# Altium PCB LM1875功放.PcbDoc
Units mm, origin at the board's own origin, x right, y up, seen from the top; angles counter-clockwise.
Board outline 134 x 60 mm, 2 copper layers (Top Layer, Bottom Layer); 94 components, 42 nets, 227 pads, 66 vias.
Unrouted connection lines stored in the file: 1.
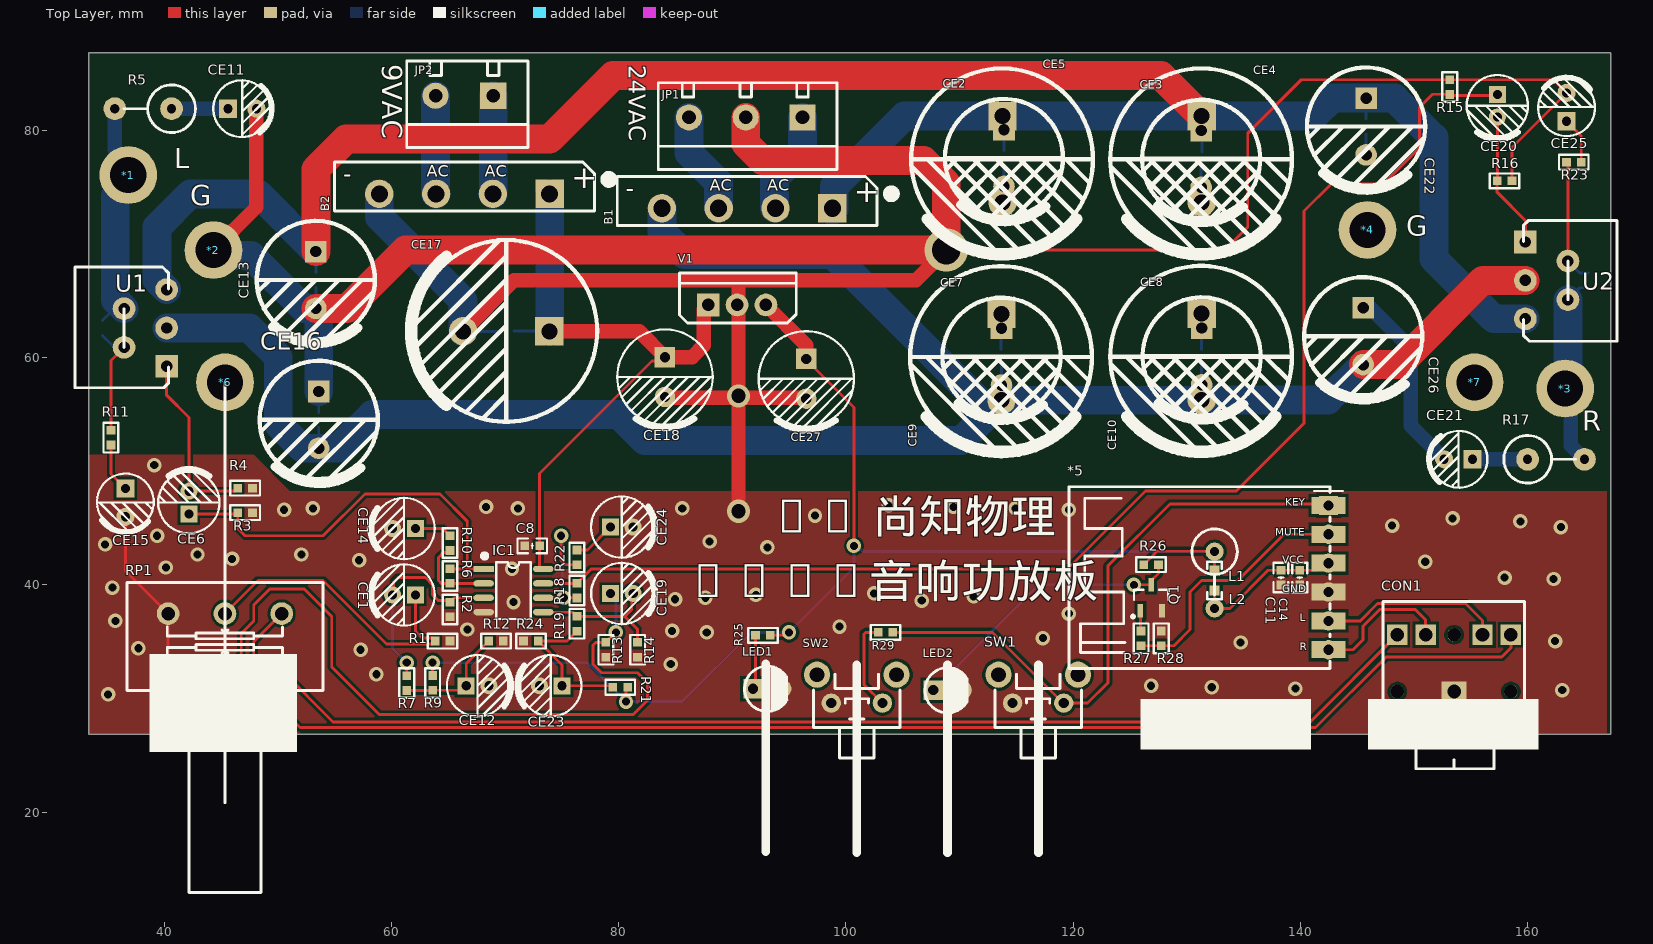
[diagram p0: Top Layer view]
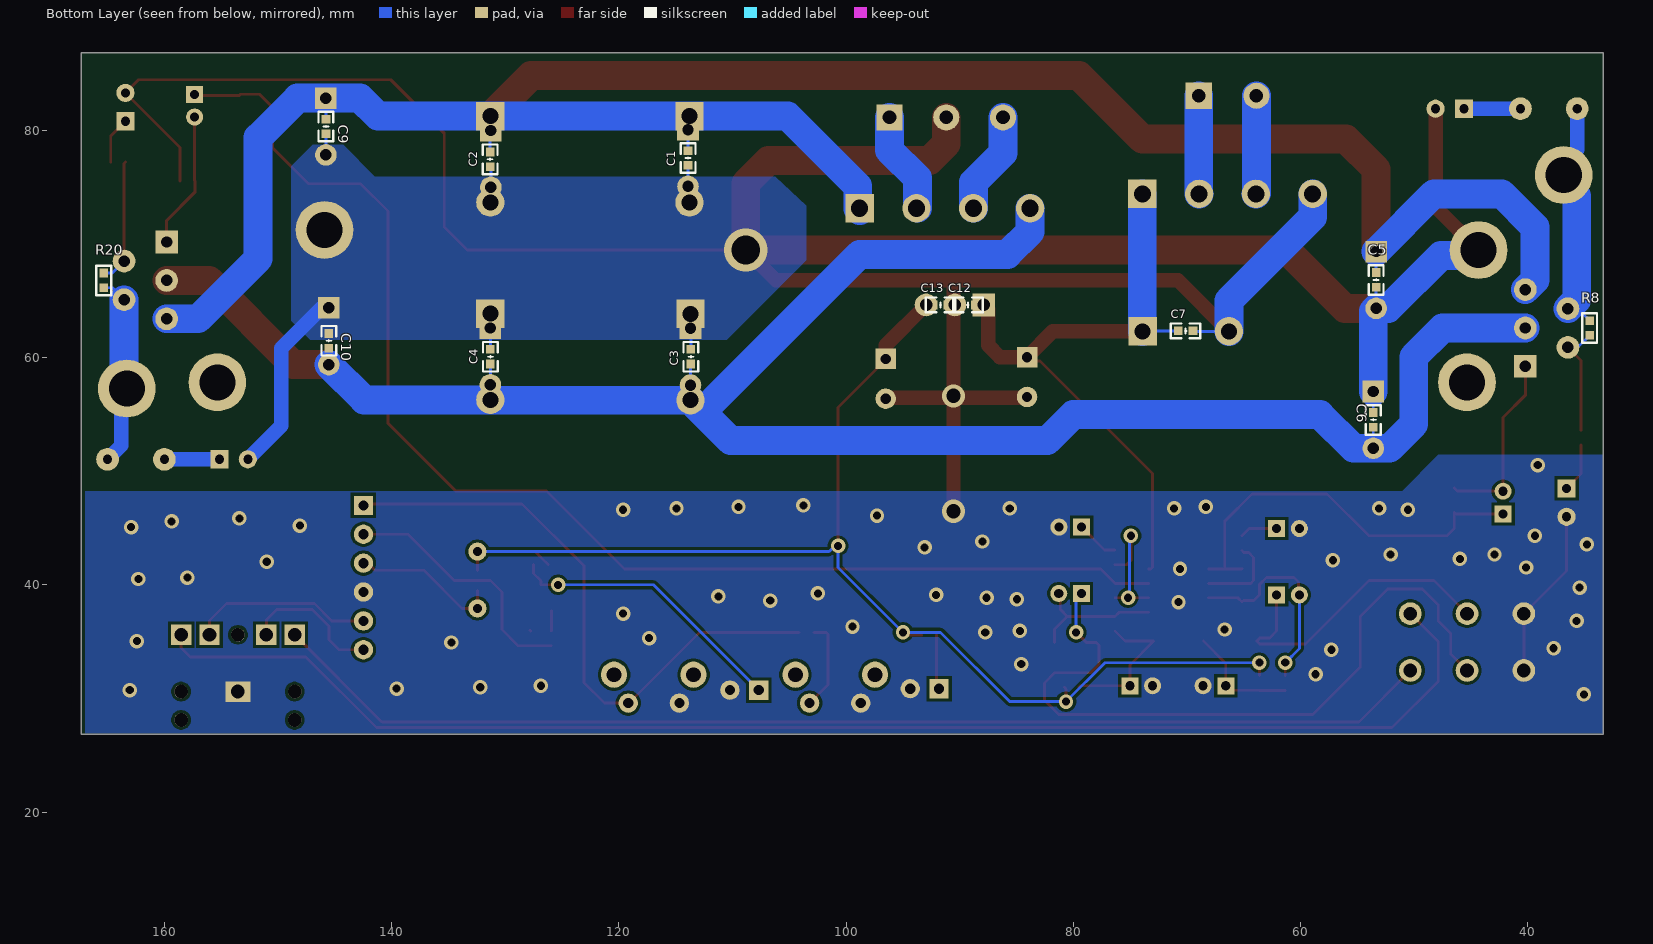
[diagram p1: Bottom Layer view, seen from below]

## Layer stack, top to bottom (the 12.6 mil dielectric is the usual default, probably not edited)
Top Solder: solder mask 0.0102, Solder Resist, Dk 3.5
Top Layer: signal copper 0.0356
Dielectric 1: dielectric 0.32, FR-4, Dk 4.8
Bottom Layer: signal copper 0.0356
Bottom Solder: solder mask 0.0102, Solder Resist, Dk 3.5

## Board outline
33.353,26.829 33.353,86.829 167.353,86.829 167.353,26.829

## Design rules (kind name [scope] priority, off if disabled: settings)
Clearance [All] p1: gap=0.254 ignorepadtopadclearanceinfootprint=FALSE except(0: Arc-Hole Track-Hole SMDPad-Hole THPad-Hole Via-Hole Fill-Hole Poly-Hole Region-Hole Text-Hole)
PlaneConnect [All] p1: planeconnectstyle=Direct reliefexpansion=0.508 reliefentries=4 reliefconductorwidth=0.254 reliefairgap=0.254
PolygonConnect [All] p1: connectstyle=Direct reliefconductorwidth=0.254 reliefentries=4 polygonreliefangle="90 Angle" airgapwidth=0.254
RoutingVias [All] p1: holewidth=0.711 width=1.27 viastyle="Through Hole" minholewidth=0.711 minwidth=1.27 maxholewidth=0.711 maxwidth=1.27
SolderMaskExpansion [All] p1: expansion=0.102 istentingtop=FALSE
Width [All] p1: maxlimit=2.54 minlimit=0.254 preferedwidth=0.254
29 further rules are at their usual default settings.

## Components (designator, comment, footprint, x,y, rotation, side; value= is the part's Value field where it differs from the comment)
*1 "M3" "M3 125X200" 36.83,76.073 r0 top
*2 "M3" "M3 125X200" 44.323,69.469 r0 top
*3 "M3" "M3 125X200" 163.322,57.277 r0 top
*4 "M3" "M3 125X200" 145.923,71.247 r0 top
*5 "MH-M18蓝牙音频模块" MH-M18蓝牙音频模块 119.634,32.639 r0 top
*6 "M3" "M3 125X200" 45.353,57.829 r0 top
*7 "M3" "M3 125X200" 155.353,57.829 r0 top
B1 "GBU" GBU 91.306,73.152 r0 top
B2 "GBU" GBU 66.428,74.422 r0 top
C1 "104" "C 0603_L" 113.919,77.577 r270 bottom
C2 "104" "C 0603_L" 131.343,77.46 r270 bottom
C3 "104" "C 0603_L" 113.665,60.086 r270 bottom
C4 "104" "C 0603_L" 131.318,60.086 r270 bottom
C5 "104" "C 0603_L" 53.34,66.842 r270 bottom
C6 "104" "C 0603_L" 53.594,54.523 r270 bottom
C7 "104" "C 0603_L" 70.119,62.357 r180 bottom
C8 "104" "C 0603_L" 72.39,43.434 r180 top
C9 "104" "C 0603_L" 145.796,80.351 r270 bottom
C10 "104" "C 0603_L" 145.542,61.483 r270 bottom
C11 "104" "C 0603_L" 138.303,40.64 r90 top
C12 "104" "C 0603_L" 89.281,64.643 r0 bottom
C13 "104" "C 0603_L" 91.694,64.643 r180 bottom
C14 "106" "C 0603_L" 139.954,40.64 r90 top
CE1 "22uF/16V" "CAP 2.0*5*11" 61.103,39.116 r180 top
CE2 "10uF/16V" "CAP 5.0*10*12.5" 113.919,77.577 r270 top
CE3 "10uF/16V" "CAP 5.0*10*12.5" 131.28,77.5 r270 top
CE4 "10uF/16V" "CAP 7.5*16*25" 131.28,77.46 r270 top
CE5 "10uF/16V" "CAP 7.5*16*25" 113.754,77.46 r270 top
CE6 "22uF/16V" "CAP 2.0*5*11" 42.164,47.244 r90 top
CE7 "10uF/16V" "CAP 5.0*10*12.5" 113.703,60.086 r270 top
CE8 "10uF/16V" "CAP 5.0*10*12.5" 131.318,60.111 r270 top
CE9 "10uF/16V" "CAP 7.5*16*25" 113.665,60.056 r270 top
CE10 "10uF/16V" "CAP 7.5*16*25" 131.28,60.081 r270 top
CE11 "0.22uF/50V" "CAP 2.5*5*11" 46.863,81.915 r0 top
CE12 "22uF/16V" "CAP 2.0*5*11" 67.58,31.115 r0 top
CE13 "470uF/25V" "CAP 5.0*10*12.5" 53.34,66.842 r270 top
CE14 "22uF/16V" "CAP 2.0*5*11" 61.103,44.958 r180 top
CE15 "22uF/16V" "CAP 2.5*5*11" 36.576,47.244 r270 top
CE16 "470uF/25V" "CAP 5.0*10*12.5" 53.594,54.523 r270 top
CE17 "10uF/16V" "CAP 7.5*16*25" 70.104,62.357 r180 top
CE18 "100uF/10V" "CAP 3.5*8*11.5" 84.074,58.293 r270 top
CE19 "22uF/16V" "CAP 2.0*5*11" 80.28,39.243 r0 top
CE20 "22uF/16V" "CAP 2.0*5*11" 157.353,82.185 r270 top
CE21 "0.22uF/50V" "CAP 2.5*5*11" 153.924,51.054 r180 top
CE22 "470uF/25V" "CAP 5.0*10*12.5" 145.796,80.351 r270 top
CE23 "22uF/16V" "CAP 2.0*5*11" 74.025,31.115 r180 top
CE24 "22uF/16V" "CAP 2.0*5*11" 80.264,45.085 r0 top
CE25 "22uF/16V" "CAP 2.5*5*11" 163.449,82.062 r90 top
CE26 "470uF/25V" "CAP 5.0*10*12.5" 145.542,61.889 r270 top
CE27 "100uF/10V" "CAP 3.5*8*11.5" 96.52,58.138 r270 top
CON1 "3F07_BK" 3F07_PK 153.543,30.607 r180 top
IC1 "NE5532" SOP8_N 70.739,39.497 r0 top
JP1 "HDR-1X3" KF301-5.0-3P 91.186,81.153 r180 top
JP2 "HDR-1X2" KF301-5.0-2P 63.881,83.058 r180 top
L1 "10uH" "L 0603" 132.461,40.386 r270 top
L2 "10uH" AL0410_V 132.461,42.926 r270 top
LED1 "红色" "LED 3MM-B" 93.091,30.861 r0 top
LED2 "红色" "LED 3MM-B" 108.966,30.734 r0 top
Q1 "SS8050" SOT23-3N 126.873,38.862 r0 top
R1 "1M" "R 0603_L" 64.501,35.052 r180 top
R2 "22K" "R 0603_L" 65.151,37.831 r90 top
R3 "1M" "R 0603_L" 47.117,46.355 r180 top
R4 "22K" "R 0603_L" 47.117,48.514 r180 top
R5 "2.2" "RS 1W-V5" 40.64,81.915 r180 top
R6 "50K" "R 0603_L" 65.151,40.782 r90 top
R7 "0" "R 0603_L" 61.341,31.354 r90 top
R8 "50K" "R 0603_L" 34.544,62.611 r270 bottom
R9 "22K" "R 0603_L" 63.627,31.369 r90 top
R10 "1K" "R 0603_L" 65.151,43.673 r90 top
R11 "1K" "R 0603_L" 35.306,52.959 r90 top
R12 "22K" "R 0603_L" 69.2,35.052 r180 top
R13 "1M" "R 0603_L" 78.867,34.29 r90 top
R14 "22K" "R 0603_L" 81.661,34.29 r90 top
R15 "1M" "R 0603_L" 153.162,83.82 r270 top
R16 "22K" "R 0603_L" 157.988,75.565 r180 top
R17 "2.2" "RS 1W-V5" 160.02,51.054 r0 top
R18 "50K" "R 0603_L" 76.327,39.497 r90 top
R19 "0" "R 0603_L" 76.327,36.576 r90 top
R20 "50K" "R 0603_L" 165.354,66.802 r90 bottom
R21 "22K" "R 0603_L" 80.137,30.988 r0 top
R22 "1K" "R 0603_L" 76.327,42.418 r90 top
R23 "1K" "R 0603_L" 164.084,77.216 r180 top
R24 "22K" "R 0603_L" 72.278,35.052 r0 top
R25 "1K" "R 0603_L" 92.695,35.56 r0 top
R26 "1K" "R 0603_L" 126.873,41.783 r0 top
R27 "1K" "R 0603_L" 125.984,35.291 r270 top
R28 "10K" "R 0603_L" 127.762,35.291 r270 top
R29 "51k" "R 0603_L" 103.49,35.814 r0 top
RP1 "100K" WH148-2-G15 45.339,35.005 r0 top
SW1 "6x6x5" "TSW DIP-6*6*6_V" 116.931,29.591 r0 top
SW2 "6x6x5" "TSW DIP-6*6*6_V" 100.965,29.591 r0 top
U1 "LM1875T" TO220-5 37.211,62.611 r90 top
U2 "LM1875T" TO220-5 162.814,66.802 r270 top
V1 "78xx" TO220A 90.424,64.643 r0 top

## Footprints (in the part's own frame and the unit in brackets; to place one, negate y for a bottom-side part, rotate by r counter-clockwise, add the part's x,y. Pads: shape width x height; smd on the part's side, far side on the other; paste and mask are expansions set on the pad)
3F07_PK [mm] "粉色，14.2*12*5mm       淘宝ID:黄晶宝石"
  rect 2.2x1.8 hole 1.2: 1(0,0)
  rect 1.8x1.8 hole 1.2: 2(5,-5) 3(2.5,-5) 4(-2.5,-5) 5(-5,-5)
  round 1.2 hole 1.2 unplated: 5(-5,0) 6(-5,2.5) 6(0,-5) 6(5,0) 6(5,2.5)
  silkscreen extent -6.18,-7.92 6.26,6.8, body extent -6,-7.7 6,6.5, height 5.6
AL0410_V [mm] "5*4*10.5mm（脚距，直径，长度）        淘宝ID:黄晶宝石"
  round 1.6 hole 0.8: 1(0,0) 2(5,0)
  silkscreen extent -2,-2 3.81,2, body extent -2.01,-2.01 5.32,2.01, height 12.39
"C 0603_L" [mil] "无极性贴片电容                                       淘宝ID:黄晶宝石"
  rect 30x30 smd: 1(-25.59,0) 2(25.59,0)
  silkscreen extent -51,-26 51,26, body extent -31,-16 31,16, height 32
"CAP 2.0*5*11" [mm] "脚距2mm直径5mm高度11mm                 淘宝ID:黄晶宝石"
  rect 1.5x1.5 hole 0.8: 1(-1,0)
  round 1.5 hole 0.8: 2(1,0)
  silkscreen extent -2.7,-2.7 2.96,2.7, body extent -2.5,-2.5 2.51,2.5, height 11.04
"CAP 2.5*5*11" [mm] "脚距2.5mm直径5mm高度11mm"
  rect 1.6x1.6 hole 0.8: 1(-1.25,0)
  round 1.6 hole 0.8: 2(1.25,0)
  silkscreen extent -2.55,-2.5 2.6,2.5, body extent -2.5,-2.5 2.51,2.5, height 11.03
"CAP 3.5*8*11.5" [mm] "脚距3.5mm直径8mm高度11.5mm"
  rect 1.8x1.8 hole 0.9: 1(-1.75,0)
  round 1.8 hole 0.9: 2(1.75,0)
  silkscreen extent -4.2,-4.2 4.5,4.2, body extent -4,-4 4.01,4, height 11.53
"CAP 5.0*10*12.5" [mm] "脚距5mm直径10mm高度12.5mm"
  rect 1.9x1.9 hole 1: 1(-2.5,0)
  round 1.9 hole 1: 2(2.5,0)
  silkscreen extent -5.2,-5.21 5.64,5.2, body extent -5,-5.01 5.01,4.99, height 12.55
"CAP 7.5*16*25" [mm] "脚距7.5mm直径16mm高度25mm"
  rect 2.5x2.5 hole 1.4: 1(-3.8,0.038)
  round 2.5 hole 1.4: 2(3.8,0.038)
  silkscreen extent -8,-8 8.42,8, body extent -8,-8 8.01,8, height 25.03
GBU [mm] "整流桥，脚距：5mm/200mil"
  round 2.5 hole 1.5: AC1(-2.5,0) AC2(2.5,0) DC-(-7.5,0)
  rect 2.5x2.5 hole 1.5: DC+(7.5,0)
  silkscreen extent -11.43,-1.52 13.06,2.79, body extent -11,-1.15 11,2.35, height 20.8
KF301-5.0-2P [mm] "可拼接端子/6A"
  rect 2.3x2.3 hole 1.2: 1(-5.08,0)
  round 2.3 hole 1.2: 2(0,0)
  silkscreen extent -8.13,-3.05 2.54,4.57, body extent -7.95,-3 2.55,4.6, height 10.05
KF301-5.0-3P [mm] "可拼接端子/6A"
  rect 2.3x2.3 hole 1.2: 1(-5,0)
  round 2.3 hole 1.2: 2(0,0) 3(5,0)
  silkscreen extent -8.05,-3.05 7.7,4.57, body extent -7.87,-3 7.63,4.6, height 10.05
"L 0603" [mil] "小功率贴片电感        淘宝ID:黄晶宝石"
  rect 35x35 smd: 1(-35,0) 2(35,0)
  silkscreen extent -65,-25 65,25, body extent -31,-16 31,16, height 31
"LED 3MM-B" [mm] "蓝色3mm直插LED                                 淘宝ID:黄晶宝石"
  rect 1.7x1.7 hole 0.9: 1(-1.27,0)
  round 1.7 hole 0.9: 2(1.27,0)
  silkscreen extent -2.01,-2 1.72,1.98, body extent -1.95,-1.95 1.64,1.95, height 5.55
"M3 125X200" [mm] "M3螺丝孔，孔125Mil，焊盘200Mil"
  round 5.08 hole 3.175: 1(0,0)
MH-M18蓝牙音频模块 [mm]
  rect 1.7x1.7 hole 0.9: 1(22.86,14.351)
  rect 3x1.5 smd: 1(22.86,14.351) 2(22.86,11.811) 3(22.86,9.271) 4(22.86,6.731) 5(22.86,4.191) 6(22.86,1.651)
  round 1.7 hole 0.9: 2(22.86,11.811) 3(22.86,9.271) 4(22.86,6.731) 5(22.86,4.191) 6(22.86,1.651)
  silkscreen extent 0,0 24.13,16, body extent 21.59,0.38 24.13,15.62, height 8.5
"R 0603_L" [mil] "1/10W贴片电阻                 淘宝ID:黄晶宝石"
  rect 30x30 smd: 1(-25.59,0) 2(25.59,0)
  silkscreen extent -51,-26 51,26, body extent -31,-16 32,16, height 16
"RS 1W-V5" [mm] "直插色环电阻，脚距5mm，直径4mm  淘宝ID:黄晶宝石"
  round 2 hole 0.8: 1(0,0) 2(5,0)
  silkscreen extent -2.1,-2.1 4.2,2.1, body extent -2.01,-2.01 5.3,2.01, height 13.3
SOP8_N [mm] "5*6*1.8mm（长宽高）封装库来自淘宝卖家 ID：黄晶宝石"
  rect 1.8x0.55 smd: 1(-2.625,1.905)
  oval 1.8x0.55 smd: 2(-2.625,0.635) 3(-2.625,-0.635) 4(-2.625,-1.905) 5(2.625,-1.905) 6(2.625,-0.635) 7(2.625,0.635) 8(2.625,1.905)
  silkscreen extent -2.69,-2.5 1.52,3.2, body extent -3,-2.5 3,2.5, height 1.9
SOT23-3N [mm] "3x1.3x1mm(长宽高)    封装库来自淘宝卖家 ID：黄晶宝石"
  rect 0.5x1.2 smd: 1(-0.95,-1.143) 2(0.95,-1.143) 3(0,1.143)
  silkscreen extent -1.72,-1.78 1.5,0.7, body extent -1.5,-1.2 1.5,1.2, height 1.05
TO220-5 [mm] "220，5    封装库来自淘宝卖家 ID：黄晶宝石"
  rect 2x2 hole 1: 1(-3.378,-3)
  round 2 hole 1: 2(-1.7,0.75) 3(0,-3) 4(1.7,0.75) 5(3.378,-3)
  silkscreen extent -5.26,-3.18 5.36,5.08, body extent -5.08,-3.25 5.08,4.99, height 21.35
TO220A [mm] "220，3脚晶体管  封装库来自淘宝卖家 ID：黄晶宝石"
  rect 2x2 hole 1.1: 1(-2.54,0)
  round 2 hole 1.1: 2(0,0) 3(2.54,0)
  silkscreen extent -5.08,-1.6 5.21,2.82, body extent -5.15,-1.53 5.15,2.9, height 18.5
"TSW DIP-6*6*6_V" [mm] "侧按轻触开关 6*6*6mm"
  round 2.3 hole 1.3: 0(-3.5,2.5) 0(3.5,2.5)
  round 1.7 hole 0.9: 1(-2.25,0) 2(2.25,0)
  silkscreen extent -3.81,-4.83 3.81,2.54, body extent -4.18,-4.72 4.18,4.13, height 7.47
WH148-2-G15 [mm] "双联电位器，脚距：5mm，柄长：15mm"
  round 2 hole 1.2: 1(-5,-2.54) 2(0,-2.54) 3(5,-2.54) 4(5,2.46) 5(0,2.46) 6(-5,2.46)
  silkscreen extent -8.64,-22.1 8.64,5.21, body extent -8.45,-22 8.45,5.01, height 20.95

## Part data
*1 *2 *3 *4 *6 *7: "铜柱孔"
B1 B2: "1KV/10A整流桥"
C1 C2 C3 C4 C5 C6 C7 C8 C9 C10 C11 C12 C13 C14: library part C, "贴片电容"
CE1 CE2 CE3 CE4 CE5 CE6 CE7 CE8 CE9 CE10 CE11 CE12 CE13 CE14 CE15 CE16 CE17 CE18 CE19 CE20 CE21 CE22 CE23 CE24 CE25 CE26 CE27: library part CE, "直插电解电容"
CON1: library part 3F07, "3.5mm耳机插座"
IC1: "双路低噪声音频运放"
JP1: library part "Header 3", "3P接插件"
JP2: library part "Header 2", "2P接插件"
L1: library part L, "小功率贴片电感"
L2: library part L-AL, "色环电感"
LED1 LED2: library part LED-3MM, "直插3mm LED"
Q1: library part 8050-SMD, "高频放大-NPN型"
R1 R2 R3 R4 R6 R7 R8 R9 R10 R11 R12 R13 R14 R15 R16 R18 R19 R20 R21 R22 R23 R24 R25 R26 R27 R28 R29: library part R, "贴片电阻"
R5 R17: library part R-S, "色环电阻"
RP1: library part RP-WH148, "双联电位器"
SW1 SW2: library part "TSW DIP-6x6_V", "侧按直插6x6轻触开关"
V1: "LM78XX系列线性稳压芯片"

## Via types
v1: diameter 1.27, hole 0.711, Top Layer to Bottom Layer, tented both sides, 63 vias
v2: diameter 2.032, hole 1.27, Top Layer to Bottom Layer, tented both sides, 2 vias
v3: diameter 3.81, hole 2.54, Top Layer to Bottom Layer, tented both sides, 1 vias

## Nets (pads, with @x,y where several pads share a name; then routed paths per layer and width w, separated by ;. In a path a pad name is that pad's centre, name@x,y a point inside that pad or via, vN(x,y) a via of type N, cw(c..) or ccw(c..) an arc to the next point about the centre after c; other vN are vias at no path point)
+5: C13.1 CE27.1 L1.1 L2.1 R9.2 R21.2 R25.2 R26.1 V1.3 | length 114.3
  Top Layer w0.254: R9.2 v1(63.627,33.147) ; v1(80.645,29.718) 80.645,30.846 R21.2 ; R25.2 94.742,35.56 v1(94.996,35.814) ; CE27.1 97.293,59.115 97.293,59.044 100.711,55.626 v1(100.711,43.434) ; R26.1 126.761,42.321 127.396,42.957 132.43,42.957 L2.1 L1.1
  Top Layer w1.27: V1.3 96.52,61.087 CE27.1
  Bottom Layer w0.254: v1(63.627,33.147) 77.216,33.147 v1(80.645,29.718) 85.598,29.718 91.694,35.814 v1(94.996,35.814) 100.711,41.529 v1(100.711,43.434) 100.986,43.434 101.494,42.926 L2.1
+9: B2.DC+ C7.1 C8.1 C12.1 CE17.1 CE18.1 IC1.8 V1.1 | length 57.9
  Top Layer w0.254: IC1.8 73.177,41.402 73.04,41.539 C8.1 73.04,49.799 82.942,59.701 83.732,59.701 CE18.1
  Top Layer w1.27: CE17.1 81.798,62.319 CE18.1 86.459,60.043 87.503,61.087 87.503,64.262 V1.1
  Bottom Layer w0.254: C7.1 73.866,62.357 CE17.1
  Bottom Layer w2.54: CE17.1 73.928,62.343 B2.DC+
+VCC: B1.DC+ C1.1 C2.1 C5.1 C9.1 CE2.1 CE3.1 CE4.1 CE5.1 CE13.1 CE22.1 U1.5 U2.5 | length 201.3
  Top Layer w2.54: CE13.1 53.34,76.581 56.007,79.248 73.914,79.248 79.502,84.836 127.742,84.836 CE4.1
  Bottom Layer w0.254: C5.1 CE13.1 ; C1.1 CE2.1 ; CE3.1 131.343,79.936 C2.1 ; C9.1 CE22.1
  Bottom Layer w2.54: U1.5 39.37,66.83 39.37,71.501 42.291,74.422 48.26,74.422 CE13.1 ; B1.DC+@98.806,72.936 98.98,73.11 98.98,75.104 105.136,81.26 CE5.1 CE4.1 141.204,81.26 142.795,82.851 CE22.1 148.289,82.851 151.765,79.375 151.765,68.707 157.048,63.424 U2.5
-VCC: B1.DC- C3.2 C4.2 C6.2 C10.2 CE7.2 CE8.2 CE9.2 CE10.2 CE16.2 CE26.2 U1.3 U2.3 | length 177.1
  Top Layer w2.54: CE26.2 148.67,59.389 156.083,66.802 U2.3
  Bottom Layer w0.254: CE16.2 C6.2 ; C3.2 113.703,59.398 CE7.2 ; CE8.2 C4.2
  Bottom Layer w2.54: U1.3 47.498,62.611 50.038,60.071 50.038,54.146 52.161,52.023 CE16.2 55.325,52.023 58.293,54.991 80.01,54.991 82.296,52.705 110.152,52.705 CE9.2 131.293,56.256 CE10.2 142.434,56.281 CE26.2 ; B1.DC- 83.806,71.084 85.802,69.088 98.806,69.088 111.638,56.256
GND: *2.1 *4.1 *5.4 B2.DC- C1.2 C2.2 C3.1 C4.1 C5.2 C6.1 C7.2 C8.2 C9.2 C10.1 C11.1 C12.2 C13.2 C14.1 CE2.2 CE3.2 CE4.2 CE5.2 CE7.1 CE8.1 CE9.1 CE10.1 CE11.2 CE12.2 CE13.2 CE14.2 CE15.2 CE16.1 CE17.2 CE18.2 CE21.2 CE22.2 CE23.2 CE24.2 CE25.2 CE26.1 CE27.2 CON1.1 IC1.4 JP1.2 LED1.2 LED2.2 Q1.2 R1.1 R2.1 R3.1 R4.1 R12.1 R13.1 R14.1 R15.1 R16.1 R24.1 R28.1 RP1.1 RP1.6 SW1.1 SW2.1 V1.2 | length 332.7
  Top Layer w0.254: CE15.2 36.576,41.228 RP1.6 RP1.1 ; v2@90.551,56.466 v2(90.551,56.642) ; v3(108.839,69.469) 133.35,69.469 135.382,71.501 135.382,79.756 140.096,84.47 R15.1 162.291,84.47 CE25.2 158.638,78.501 R16.1 ; R28.1 R28.1@127.823,36.002
  Top Layer w1.27: *2.1 48.113,73.259 CE11.2 ; CE17.2 70.787,66.802 90.551,66.802 ; CE18.2 84.151,56.466 v2@90.551,56.466 ; v2(90.551,46.482) v2@90.551,56.466 ; v2(90.551,56.642) 90.551,64.516 V1.2 90.551,64.77 90.551,66.802 ; CE27.2 96.442,56.466 v2@90.551,56.466 ; v3(108.839,69.469) 106.172,66.802 90.551,66.802
  Top Layer w2.54: CE13.2 56.087,64.342 61.214,69.469 v3@107.173,69.469 ; JP1.2 91.186,78.831 92.674,77.343 106.843,77.343 108.839,75.347 v3(108.839,69.469)
  Bottom Layer w0.254: CE13.2 C5.2 ; C6.1 CE16.1 ; CE17.2 69.431,62.319 C7.2 ; C3.1 113.665,62.548 CE7.1 ; CE2.2 C1.2 ; CE3.2 131.28,76.746 C2.2 ; C4.1 CE8.1 ; CE22.2 C9.2
  Bottom Layer w1.27: CE26.1@146.177,64.389 149.733,60.833 149.733,53.995 CE21.2
  Bottom Layer w2.54: *2.1 44.809,68.983 47.632,68.983 52.273,64.342 CE13.2 53.594,64.088 CE16.1 ; B2.DC- 58.928,72.39 66.304,65.014 CE17.2
  other v1: 35.052,30.353 163.068,30.734 139.573,30.861 132.207,30.988 126.873,31.115 58.674,32.131 84.582,33.02 57.277,34.29 37.719,34.417 134.747,34.925 162.433,35.052 117.348,35.306 87.757,35.814 84.709,35.941 66.675,36.068 99.441,36.322 35.687,36.83 119.634,37.465 70.739,38.481 106.68,38.608 84.963,38.735 87.63,38.862 111.252,38.989 92.075,39.116 102.489,39.243 35.433,39.751 162.306,40.513 157.988,40.64 70.612,41.402 40.132,41.529 151.003,42.037 57.15,42.164 45.974,42.291 42.926,42.672 52.07,42.672 93.091,43.307 34.798,43.561 88.011,43.815 39.37,44.323 162.941,45.085 148.082,45.212 159.385,45.593 153.416,45.847 97.282,46.101 50.546,46.609 119.634,46.609 53.086,46.736 71.12,46.736 85.598,46.736 114.935,46.736 68.326,46.863 109.474,46.863 103.759,46.99 39.116,50.546
Lout: *1.1 R5.2 R8.1 U1.4 | length 21.2
  Bottom Layer w0.254: R8.1 35.26,63.977 36.127,63.977 U1.4
  Bottom Layer w1.27: R5.2 35.64,78.294 36.83,77.104 *1.1
  Bottom Layer w2.54: U1.4 35.687,65.085 35.687,74.243 36.83,75.386 *1.1
Net*5_1: *5.1 R29.2 SW1.2 | length 54.3
  Top Layer w0.254: R29.2 112.903,35.814 119.126,29.591 121.285,29.591 123.063,31.369 123.063,41.656 128.524,47.117 142.367,47.117 *5.1@142.494,46.99
Net*5_2: *5.2 R27.2 R28.2 | length 22.5
  Top Layer w0.254: R27.2 R28.2 128.875,34.641 130.302,36.068 130.302,39.37 131.318,40.386 134.493,40.386 138.557,44.45 *5.2@142.494,44.45
Net*5_3: *5.3 C11.2 C14.2 L1.2 L2.2 | length 13.3
  Top Layer w0.254: L1.2 L2.2 133.811,37.926 137.175,41.29 C11.2 C14.2 141.483,41.29 142.103,41.91 *5.3@142.494,41.91
Net*5_5: *5.5 CON1.4 | length 16.1
  Top Layer w0.254: *5.5@142.494,36.83 145.288,36.83 146.812,38.354 154.559,38.354 156.043,36.87 CON1.4
Net*5_6: *5.6 CON1.3 | length 12.4
  Top Layer w0.254: *5.6@142.494,34.29 144.653,34.29 145.542,35.179 145.542,36.366 147.022,37.846 150.114,37.846 151.043,36.917 CON1.3
NetB1_AC1: B1.AC1 JP1.3 | length 9.1
  Bottom Layer w2.54: JP1.3 86.186,78.025 88.773,75.438 B1.AC1@88.773,73.152
NetB1_AC2: B1.AC2 JP1.1 | length 9
  Bottom Layer w2.54: B1.AC2@93.726,73.183 93.726,75.819 96.186,78.279 JP1.1
NetB2_AC1: B2.AC1 JP2.2 | length 8.7
  Bottom Layer w2.54: JP2.2 63.881,74.469 B2.AC1
NetB2_AC2: B2.AC2 JP2.1 | length 8.6
  Bottom Layer w2.54: B2.AC2 68.961,74.455 JP2.1
NetCE1_1: CE1.1 R1.2 RP1.5 | length 27.4
  Top Layer w0.254: RP1.5 48.26,40.386 53.975,40.386 59.563,34.798 63.597,34.798 R1.2 63.597,35.306 62.738,35.306 62.103,35.941 CE1.1
NetCE1_2: CE1.2 IC1.3 R2.2 R7.2 | length 18.5
  Top Layer w0.254: CE1.2 60.186,39.199 60.186,40.247 60.579,40.64 62.992,40.64 63.627,40.005 63.627,39.116 64.135,38.608 65.024,38.608 R2.2 65.532,38.862 IC1.3 ; R7.2 v1(61.341,33.147)
  Bottom Layer w0.254: CE1.2 60.103,34.385 v1(61.341,33.147)
NetCE6_1: CE6.1 IC1.1 R3.2 R6.2 | length 35.9
  Top Layer w0.254: CE6.1 46.356,46.244 R3.2 46.467,44.973 47.117,44.323 53.975,44.323 57.658,48.006 64.262,48.006 66.675,45.593 66.675,41.429 66.648,41.402 ; R6.2 65.181,41.402 66.648,41.402 ; IC1.1 66.648,41.402
NetCE6_2: CE6.2 R4.2 U1.1 | length 16.2
  Top Layer w0.254: U1.1 40.211,56.693 42.164,54.74 CE6.2 42.18,48.26 46.213,48.26 R4.2
NetCE11_1: CE11.1 R5.1 | length 5
  Bottom Layer w1.27: R5.1 CE11.1
NetCE12_1: CE12.1 R7.1 R9.1 R12.2 | length 10.2
  Top Layer w0.254: R7.1 63.612,30.704 R9.1 66.184,30.719 CE12.1 66.58,33.082 R12.2
NetCE14_1: CE14.1 R10.2 | length 3.3
  Top Layer w0.254: CE14.1 64.516,44.958 R10.2
NetCE15_1: CE15.1 R11.1 | length 4.3
  Top Layer w0.254: R11.1 35.306,49.764 CE15.1
NetCE19_1: CE19.1 R13.2 RP1.2 | length 64.6
  Top Layer w0.254: RP1.2 46.776,33.902 46.776,35.727 47.879,36.83 47.879,38.227 49.276,39.624 52.324,39.624 54.737,37.211 54.737,32.766 58.928,28.575 81.28,28.575 82.55,29.845 82.55,31.369 81.661,32.258 78.486,32.258 77.724,33.02 77.724,34.671 77.993,34.94 R13.2 79.741,35.814 v1(79.756,35.814)
  Bottom Layer w0.254: CE19.1 79.756,38.767 v1(79.756,35.814)
NetCE19_2: CE19.2 IC1.5 R14.2 R19.2 | length 12.4
  Top Layer w0.254: IC1.5 75.961,37.592 R19.2 80.533,37.226 ; CE19.2 81.153,39.116 81.153,37.846 80.533,37.226 ; R14.2 81.661,36.098 80.533,37.226
NetCE20_1: CE20.1 IC1.7 R15.2 R18.2 | length 114.9
  Top Layer w0.254: IC1.7 76.312,40.132 R18.2 77.582,41.402 119.507,41.402 126.365,48.26 134.366,48.26 140.335,54.229 140.335,72.898 142.748,75.311 147.32,75.311 150.495,78.486 150.495,82.042 151.638,83.185 153.304,83.185 153.416,83.073 157.241,83.073 CE20.1
NetCE20_2: CE20.2 R16.2 U2.1 | length 12
  Top Layer w0.254: CE20.2 157.353,75.58 R16.2 157.338,74.564 159.814,72.088 U2.1
NetCE21_1: CE21.1 R17.1 | length 4.8
  Bottom Layer w1.27: CE21.1 R17.1
NetCE23_1: CE23.1 R19.1 R21.1 R24.2 | length 13.1
  Top Layer w0.254: R19.1 75.453,35.052 R24.2 75.025,32.955 CE23.1 79.36,31.115 R21.1
NetCE24_1: CE24.1 R22.2 | length 3.8
  Top Layer w0.254: R22.2 77.247,43.068 CE24.1
NetCE25_1: CE25.1 R23.1 | length 4.1
  Top Layer w0.254: CE25.1 164.734,79.527 R23.1
NetCON1_2: CON1.2 RP1.3 | length 103.3
  Top Layer w0.254: RP1.3 54.864,27.94 140.876,27.94 CON1.2
NetCON1_5: CON1.5 RP1.4 | length 123.4
  Top Layer w0.254: RP1.4 47.879,35.005 47.879,31.496 51.943,27.432 141.351,27.432 147.574,33.655 157.734,33.655 158.543,34.464 CON1.5@158.543,35.607
NetIC1_2: IC1.2 R6.1 R10.1 | length 7.4
  Top Layer w0.254: R10.1 64.96,42.832 64.549,42.832 64.135,42.418 64.135,40.386 64.389,40.132 R6.1 IC1.2
NetIC1_6: IC1.6 R18.1 R22.1 | length 12.3
  Top Layer w0.254: IC1.6 v1(75.184,38.862) 76.312,38.862 R18.1 ; v1(74.93,44.323) 74.93,42.164 75.326,41.768 R22.1
  Bottom Layer w0.254: v1(74.93,44.323) 75.057,44.196 75.057,38.989 v1(75.184,38.862)
NetLED1_1: LED1.1 R25.1 | length 4.8
  Top Layer w0.254: LED1.1 92.045,31.085 R25.1
NetLED2_1: LED2.1 Q1.3 R26.2 | length 25.1
  Top Layer w0.254: v1(125.349,40.005) Q1.3 126.873,40.355 127.523,41.005 R26.2
  Bottom Layer w0.254: LED2.1 116.967,40.005 v1(125.349,40.005)
NetQ1_1: Q1.1 R27.1 | length 1.8
  Top Layer w0.254: Q1.1 125.923,36.002 R27.1
NetR8_2: R8.2 R11.2 U1.2 | length 10.5
  Top Layer w0.254: R11.2 35.306,59.756 U1.2
  Bottom Layer w0.254: R8.2 35.433,61.072 35.431,61.072 36.354,60.149 U1.2@36.461,60.149
NetR20_2: R20.2 R23.2 U2.2 | length 11
  Top Layer w0.254: R23.2 163.564,77.086 U2.2
  Bottom Layer w0.254: U2.2 164.614,67.452 R20.2
NetR29_1: R29.1 SW2.2 | length 8
  Top Layer w0.254: R29.1 101.749,35.814 101.6,35.665 101.6,31.206 SW2.2
Rout: *3.1 R17.2 R20.1 U2.4 | length 17.1
  Bottom Layer w0.254: U2.4 164.614,66.152 R20.1
  Bottom Layer w1.27: *3.1@163.808,56.791 163.808,52.266 R17.2
  Bottom Layer w2.54: U2.4 163.564,57.519 *3.1 *3.1@163.808,56.791
pads on no net: *6.1 *7.1 CON1.6 SW1.0 SW2.0

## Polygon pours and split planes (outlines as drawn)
GND on Bottom Layer "NONET_L-01_P-001" (solid, pour order 1): 33.401,51.435 47.879,51.435 51.054,48.26 148.463,48.26 166.972,48.26 166.972,26.924 33.401,26.924
GND on Bottom Layer "NONET_L-01_P-001" (solid, pour order 0): 106.232,75.946 141.478,75.946 144.272,78.74 146.939,78.74 148.844,76.835 148.844,63.246 147.193,61.595 110.49,61.595 103.505,68.58 103.505,73.371
GND on Top Layer "NONET_L-01_P-001" (solid, pour order 2): 33.401,51.435 47.879,51.435 51.054,48.26 148.463,48.26 166.972,48.26 166.972,26.924 33.401,26.924

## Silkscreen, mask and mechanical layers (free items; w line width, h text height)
Top Overlay:
  rectangle: 145.954,25.497 160.954,29.942
  rectangle: 125.954,25.497 140.954,29.942
  rectangle: 38.689,25.273 51.689,33.909
  lines w0.254: 45.353,20.814 45.353,57.829
  lines w0.762: 92.936,16.522 92.936,33.032 ; 100.954,16.432 100.954,32.942 ; 108.954,16.432 108.954,32.942 ; 116.954,16.432 116.954,32.942
  text "9VAC" at 58.581,85.852 h3.05 r270
  text "24VAC" at 80.419,85.727 h2.54 r270
  text "L" at 40.894,76.073 h3.05
  text "G" at 42.291,72.805 h3.05
  text "G" at 149.352,70.138 h3.05
  text "R" at 164.846,52.959 h3.05
  text "By 尚知物理" at 93.218,43.626 h5.08
  text "1875音响功放板" at 85.852,37.945 h5.08
Mechanical 1:
  the board outline again, w0.762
